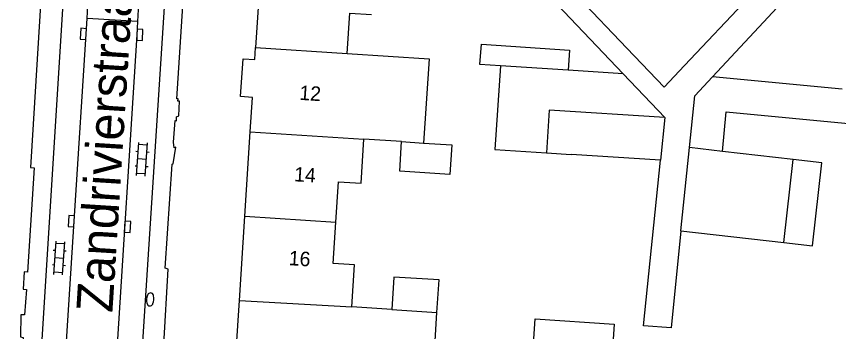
# Model space of a CAD drawing. Extents: x 132994 to 136000, y 393499 to 395512.
# Drawn here: x 133059 to 133115.8, y 395243.6 to 395265.4 of the extents above; entities that cross this region are included whole.
import ezdxf

# ---------------------------------------------------------------- set-up
doc = ezdxf.new("R2010")
doc.units = 0
for name, color, linetype in [('gg-afsc-erfafscheiding', 7, 'Continuous'), ('gg-anno-huisnummerreeks BGT', 7, 'Continuous'), ('gg-anno-openbare ruimte label', 7, 'Continuous'), ('gg-bbg-gedigitaliseerde bebouwing', 7, 'Continuous'), ('gg-bbg-gedigitaliseerde bijgebouw', 7, 'Continuous'), ('gg-bbg-hoofdgebouw', 7, 'Continuous'), ('gg-bbg-luifel en loopbrug', 7, 'Continuous'), ('gg-bbg-tussenscheiding', 7, 'Continuous'), ('gg-knt-verharding', 7, 'Continuous'), ('gt-symb-brandkraan', 7, 'Continuous'), ('gt-symb-klinker verharding', 7, 'Continuous'), ('gt-symb-kolk', 7, 'Continuous')]:
    doc.layers.add(name, color=color, linetype=linetype)

# ---------------------------------------------------------------- blocks, each defined once
blk = doc.blocks.new('gt0-KL1')
at = {"layer": 'gt-symb-klinker verharding'}
for p, q in [((-1.15, 0.3), (1.15, 0.3)), ((-1, -0.3), (-1, 0.3)), ((-0.5, 0.3), (-0.5, 0.45)), ((0, -0.3), (0, 0.3)), ((0.5, 0.3), (0.5, 0.45)), ((1, -0.3), (1, 0.3)), ((-1.15, -0.3), (1.15, -0.3)), ((-0.5, -0.45), (-0.5, -0.3)), ((0.5, -0.45), (0.5, -0.3))]:
    blk.add_line(p, q, dxfattribs=at)
blk = doc.blocks.new('gt0-KOLK')
at = {"layer": 'gt-symb-kolk'}
blk.add_lwpolyline([(0, 0), (0.375, 0), (0.375, 0.4), (-0.375, 0.4), (-0.375, 0), (0, 0)], dxfattribs=at)
blk = doc.blocks.new('gt0-BR')
at = {"layer": 'gt-symb-brandkraan'}
for centre, radius, start, end in [((-0.244, 0), 0.206, 107.5669, 252.4331), ((0.599, -2.664), 3, 106.892, 107.5669), ((0, -0.691), 0.938, 73.108, 106.892), ((-0.599, -2.664), 3, 72.4331, 73.108), ((0.244, 0), 0.206, 287.567, 72.4331), ((0.599, 2.664), 3, 252.4331, 253.108), ((0, 0.691), 0.938, 253.108, 286.8921), ((-0.599, 2.664), 3, 286.8921, 287.567)]:
    blk.add_arc(centre, radius, start, end, dxfattribs=at)

msp = doc.modelspace()

# ---------------------------------------------------------------- linework, layer by layer
at = {"layer": 'gg-afsc-erfafscheiding'}
for p, q in [((133113.634, 395270.992), (133105.118, 395261.98)), ((133100.886, 395261.397), (133094.441, 395268.179)), ((133101.126, 395263.177), (133097.441, 395267.057))]:
    msp.add_line(p, q, dxfattribs=at)
for points in [[(133105.118, 395261.98), (133103.704, 395260.464), (133101.126, 395263.177)], [(133104.877, 395250.54), (133104.199, 395243.851), (133102.293, 395243.975), (133103.454, 395255.433)]]:
    msp.add_lwpolyline(points, dxfattribs=at)
at = {"layer": 'gg-bbg-gedigitaliseerde bebouwing'}
for p, q in [((133085.58, 395256.711), (133082.982, 395256.88)), ((133084.906, 395245.111), (133082.148, 395245.288))]:
    msp.add_line(p, q, dxfattribs=at)
for points in [[(133081.831, 395262.808), (133082.008, 395265.595), (133083.509, 395265.499)], [(133081.831, 395262.808), (133087.476, 395262.441), (133087.097, 395256.612)], [(133081.042, 395251.154), (133081.22, 395253.944), (133082.788, 395253.844), (133082.982, 395256.88)], [(133082.148, 395245.288), (133082.334, 395248.192), (133080.859, 395248.286), (133081.042, 395251.154)], [(133080.346, 395239.475), (133084.572, 395239.204), (133084.774, 395242.354), (133087.843, 395242.157), (133088.019, 395244.905)]]:
    msp.add_lwpolyline(points, dxfattribs=at)
at = {"layer": 'gg-bbg-gedigitaliseerde bijgebouw'}
for p, q in [((133112.283, 395266.799), (133107.052, 395261.194)), ((133103.753, 395258.378), (133103.454, 395255.433)), ((133095.577, 395255.937), (133097.302, 395255.825)), ((133104.877, 395250.54), (133105.461, 395256.298)), ((133112.633, 395255.477), (133107.737, 395256.037)), ((133103.454, 395255.433), (133097.302, 395255.825)), ((133111.977, 395249.741), (133112.633, 395255.477)), ((133104.877, 395250.54), (133111.977, 395249.741))]:
    msp.add_line(p, q, dxfattribs=at)
for points in [[(133105.461, 395256.298), (133105.824, 395259.878), (133107.052, 395261.194)], [(133107.737, 395256.037), (133107.997, 395258.768), (133121.264, 395257.508), (133121.484, 395259.822), (133119.856, 395259.977)], [(133103.753, 395258.378), (133095.77, 395258.897), (133095.577, 395255.937)], [(133087.097, 395256.612), (133089.052, 395256.484), (133088.92, 395254.439), (133085.448, 395254.663), (133085.58, 395256.711)], [(133088.019, 395244.905), (133088.164, 395247.159), (133085.05, 395247.359), (133084.906, 395245.111)], [(133094.574, 395240.992), (133094.798, 395244.464), (133100.251, 395244.112), (133100.027, 395240.64), (133094.574, 395240.992)]]:
    msp.add_lwpolyline(points, dxfattribs=at)
at = {"layer": 'gg-bbg-hoofdgebouw'}
for p, q in [((133075.86, 395268.92), (133075.497, 395263.22)), ((133074.754, 395251.564), (133075.125, 395257.392)), ((133074.382, 395245.735), (133074.754, 395251.564)), ((133074.011, 395239.906), (133074.382, 395245.735))]:
    msp.add_line(p, q, dxfattribs=at)
msp.add_lwpolyline([(133075.125, 395257.392), (133075.277, 395259.77), (133074.463, 395259.821), (133074.628, 395262.428), (133075.443, 395262.377), (133075.497, 395263.22)], dxfattribs=at)
at = {"layer": 'gg-bbg-luifel en loopbrug'}
for p, q in [((133097.076, 395261.645), (133092.404, 395261.949)), ((133100.886, 395261.397), (133097.076, 395261.645)), ((133100.886, 395261.397), (133103.753, 395258.378))]:
    msp.add_line(p, q, dxfattribs=at)
for points in [[(133092.404, 395261.949), (133090.995, 395262.045), (133091.091, 395263.455), (133097.172, 395263.039), (133097.076, 395261.645)], [(133092.404, 395261.949), (133092.028, 395256.168), (133095.577, 395255.937)], [(133111.977, 395249.741), (133113.962, 395249.518), (133114.606, 395255.256), (133112.633, 395255.477)]]:
    msp.add_lwpolyline(points, dxfattribs=at)
at = {"layer": 'gg-bbg-tussenscheiding'}
for p, q in [((133075.497, 395263.22), (133081.831, 395262.808)), ((133116.013, 395260.342), (133107.052, 395261.194)), ((133075.125, 395257.392), (133082.982, 395256.88)), ((133085.58, 395256.711), (133087.097, 395256.612)), ((133107.737, 395256.037), (133105.461, 395256.298)), ((133074.754, 395251.564), (133081.042, 395251.154)), ((133074.382, 395245.735), (133082.148, 395245.288)), ((133084.906, 395245.111), (133088.019, 395244.905))]:
    msp.add_line(p, q, dxfattribs=at)
at = {"layer": 'gg-knt-verharding'}
for p, q in [((133067.551, 395268.611), (133067.337, 395265.003)), ((133063.863, 395265.224), (133063.918, 395266.137)), ((133067.337, 395265.003), (133063.863, 395265.224))]:
    msp.add_line(p, q, dxfattribs=at)
for points in [[(133061.589, 395281.532), (133059.955, 395254.921), (133060.204, 395254.905), (133059.754, 395247.702), (133059.505, 395247.717), (133059.433, 395246.518), (133059.677, 395246.494), (133059.542, 395244.735), (133059.292, 395244.754), (133059.248, 395243.22), (133059.454, 395243.182), (133059.236, 395239.609), (133058.986, 395239.624), (133058.979, 395239.513)], [(133064.395, 395218.4), (133066.115, 395218.323), (133070.146, 395280.604)], [(133068.55, 395232.29), (133069.452, 395247.911), (133069.25, 395247.971), (133069.743, 395255.147), (133069.8, 395255.18), (133069.979, 395256.327), (133069.875, 395256.295), (133069.826, 395256.676), (133069.931, 395258.161), (133070.03, 395258.154), (133070.043, 395258.434), (133070.198, 395258.499), (133070.24, 395259.512), (133070.131, 395259.512), (133070.142, 395259.663), (133070.055, 395259.66), (133070.512, 395266.835), (133070.679, 395266.842), (133070.789, 395267.844), (133070.668, 395267.859), (133070.877, 395269.079), (133070.95, 395270.26)], [(133063.918, 395266.137), (133062.188, 395266.233), (133060.399, 395237.872), (133062.133, 395237.758)], [(133062.133, 395237.758), (133062.237, 395239.648), (133062.965, 395251.208), (133063.863, 395265.224)], [(133067.337, 395265.003), (133067.299, 395264.099), (133064.395, 395218.4)]]:
    msp.add_lwpolyline(points, dxfattribs=at)

# ---------------------------------------------------------------- block references
at = {"layer": 'gt-symb-brandkraan', "rotation": 85.35527839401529}
msp.add_blockref('gt0-BR', (133068.217, 395245.81), dxfattribs=at)
at = {"layer": 'gt-symb-klinker verharding'}
for p, rotation in [((133067.654, 395255.494), 86.3879250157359), ((133061.94, 395248.665), 86.33074590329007)]:
    msp.add_blockref('gt0-KL1', p, dxfattribs=dict(at, rotation=rotation))
at = {"layer": 'gt-symb-kolk'}
for p, rotation in [((133063.793, 395264.14), 86.3307459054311), ((133067.299, 395264.099), -92.40741384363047), ((133062.965, 395251.208), 86.3879250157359), ((133066.448, 395250.836), -93.6692540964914)]:
    msp.add_blockref('gt0-KOLK', p, dxfattribs=dict(at, rotation=rotation))

# ---------------------------------------------------------------- texts
at = {"layer": 'gg-anno-huisnummerreeks BGT'}
for s, p in [('12', (133078.496, 395259.602)), ('14', (133078.137, 395253.975)), ('16', (133077.768, 395248.181))]:
    msp.add_text(s, height=1, rotation=356.3, dxfattribs=at).set_placement(p)
at = {"layer": 'gg-anno-openbare ruimte label'}
msp.add_text('Zandrivierstraat', height=2.5, rotation=86.4, dxfattribs=at).set_placement((133065.603, 395244.862))

doc.saveas('drawing.dxf')
